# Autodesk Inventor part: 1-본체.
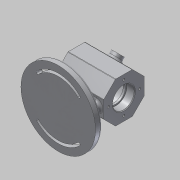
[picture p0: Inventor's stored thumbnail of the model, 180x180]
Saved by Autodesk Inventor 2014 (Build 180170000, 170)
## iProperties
Created: 2017-06
Part Number: 1-본체.
Material: Aluminum 6061
Document SubType Name: Modeling
Designer: Administrator
Density: 2.71 g/cm^3
Appearance: Aluminum - Flat
Mass: 562.518 g
Surface Area: 565.55 cm^2
Volume: 207.571 cm^3
Author: Administrator
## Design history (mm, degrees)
sketch "Sketch1"
  geometry: L1 (92, -12.426)-(74.426, -30); L2 (74.426, -30)-(49.574, -30); L3 (49.574, -30)-(32, -12.426); L4 (32, -12.426)-(32, 12.426); L5 (32, 12.426)-(49.574, 30); L6 (49.574, 30)-(74.426, 30); L7 (74.426, 30)-(92, 12.426); L8 (92, 12.426)-(92, -12.426); L9 (92, -12.426)-(62, 0); L10 (92, 12.426)-(62, 0); C1 r 30 at (62, 0); 1 further point
  constraints: 20 end point, 1 centre point, 1 coincident, 1 horizontal, 1 tangent, 17 other
  dimensions: "d2" = 60 diameter of C1; "d3" = 45 deg angle of L10 L9 (derived); "d4" = 62 distance of C1.centre point (0, 0); "d5" = 92 horizontal distance of point (0, 0) L1.start
extrude "Extrusion1" new body sketch "Sketch1" stored distance "d6" = 70; taper "d7" = 0 deg
sketch "Sketch2"
  geometry: C1 r 55 at (0, 0); 1 further point
  constraints: 1 centre point, 1 coincident
  dimensions: "d8" = 110 diameter of C1
extrude "Extrusion2" join sketch "Sketch2" distance "d9" = 10; taper "d10" = 0 deg
sketch "Sketch3"
  geometry: L1 (-35, 62)-(35, 62); L2 (-35, 62)-(-35, 78); L3 (-35, 78)-(-23, 78); L4 (-23, 78)-(-23, 76); L5 (-23, 76)-(-20, 76); L6 (-20, 76)-(-20, 87); L7 (-20, 87)-(20, 87); L8 (20, 87)-(20, 76); L9 (20, 76)-(23, 76); L10 (23, 76)-(23, 78); L11 (23, 78)-(35, 78); L12 (35, 78)-(35, 62); 1 further point
  constraints: 24 end point, 11 perpendicular, 1 horizontal
  dimensions: "d12" = 12 distance of L2.end L3.end; "d14" = 3 distance of L5.end L4.end; "d16" = 40 distance of L6.end L7.end; "d17" = 3 distance of L8.end L9.end; "d19" = 32 diameter of L2.end L1; "d21" = 28 diameter of L4.end L1; "d22" = 50 diameter of L6.end L1; "d23" = 32 diameter of L11.end L1; "d24" = 28 diameter of L9.end L1; "d25" = 12 distance between parallel lines of L12 L10; "d26" = 35 distance from line of point (0, 0) L12; "d27" = 78 distance from line of point (0, 0) L11
revolve "Revolution1" sketch "Sketch3" stored, may be unused: angle "d28" = 90 deg
sketch "Sketch4"
  geometry: 5 further points
sketch "Sketch5"
  geometry: 5 further points
hole "Hole1" sketch "Sketch4" diameter "d31" = 3.242; stored, may be unused: countersink angle "d35" = 90 deg, drill point angle "d37" = 118 deg; dims "d32" = 8, "d33" = 4, "d34" = 2, "d36" = 10
hole "Hole2" sketch "Sketch5" diameter "d38" = 3.242; stored, may be unused: countersink angle "d42" = 90 deg, drill point angle "d44" = 118 deg; dims "d39" = 8, "d40" = 4, "d41" = 2, "d43" = 10
workplane "Work Plane1"
sketch "Sketch6"
  geometry: C1 r 8 at (35, 12.426); 2 further points
  constraints: 1 centre point
  dimensions: "d47" = 16 diameter of C1; "d48" = 35 horizontal distance of C1.centre point (0, 24.853); "d49" = 43.84062 distance of point (35, -31.414) C1.centre
extrude "Extrusion3" join sketch "Sketch6" stored distance "d50" = 10; taper "d51" = 0 deg
sketch "Sketch7"
  geometry: C1 r 4 at (0, 0); C2 r 8 at (0, 0) reference; 1 further point
  constraints: 1 centre point, 1 concentric
  dimensions: "d52" = 8 diameter of C1
extrude "Extrusion4" cut sketch "Sketch7" distance "d53" = 20; taper "d54" = 0 deg
sketch "Sketch8"
  geometry: C1 r 55 at (0, 0) reference; A1 r 2 centre (-30.406, 30.406) between (-31.82, 31.82) and (-28.991, 28.991); A2 r 2 centre (30.406, 30.406) between (28.991, 28.991) and (31.82, 31.82); A3 r 45 centre (0, 0) between (31.82, 31.82) and (-31.82, 31.82); A4 r 41 centre (0, 0) between (28.991, 28.991) and (-28.991, 28.991)
  constraints: 8 point on circle, 4 centre point, 4 tangent, 1 coincident, 1 concentric
  dimensions: "d62" = 2 radius of A2; "d63" = 45 radius of A3; "d64" = 60.87693 distance of A2.end A1.end
extrude "Extrusion5" cut sketch "Sketch8" distance "d65" = 7; taper "d66" = 0 deg
sketch "Sketch9"
  geometry: C1 r 55 at (0, 0) reference; A1 r 5 centre (30.406, -30.406) between (33.941, -33.941) and (26.87, -26.87); A2 r 5 centre (-30.406, -30.406) between (-26.87, -26.87) and (-33.941, -33.941); A3 r 38 centre (0, 0) between (-26.87, -26.87) and (26.87, -26.87); A4 r 48 centre (0, 0) between (-33.941, -33.941) and (33.941, -33.941)
  constraints: 8 point on circle, 4 centre point, 3 tangent, 1 coincident, 1 concentric
  dimensions: "d72" = 10 diameter of A1; "d73" = 10 diameter of A2; "d74" = 48 radius of A4; "d78" = 61.22091 distance of A1.start A2.start
extrude "Extrusion6" cut sketch "Sketch9" distance "d76" = 3; taper "d77" = 0 deg
mirror "Mirror1"
sketch "Sketch10"
  geometry: L1 (-24, 5)-(24, 5); L2 (-24, -5)-(24, -5); A1 r 5 centre (-24, 0) between (-24, 5) and (-24, -5); A2 r 5 centre (24, 0) between (24, -5) and (24, 5); 1 further point
  constraints: 4 end point, 4 point on circle, 4 tangent, 2 centre point, 1 horizontal
  dimensions: "d81" = 10 diameter of A1; "d82" = 10 diameter of A2; "d83" = 48 distance of A2.centre A1.centre; "d84" = 28.94113 distance from line of point (33.941, 33.941) L1; "d85" = 38.94113 distance from line of point (33.941, 33.941) L2
extrude "Extrusion7" join sketch "Sketch10" stored distance "d86" = 3; taper "d87" = 0 deg
chamfer "Chamfer1" distance "d88" = 1; stored, may be unused: second distance "d89" = 2, angle "d90" = 45 deg
chamfer "Chamfer2" distance "d91" = 1; stored, may be unused: second distance "d92" = 2, angle "d93" = 45 deg
chamfer "Chamfer3" distance "d96" = 1; stored, may be unused: second distance "d97" = 2, angle "d98" = 45 deg
fillet "Fillet1" dims "d94" = 3, "d95" = 0.3, "d99" = 5, "d104" = 1
sketch "Sketch11"
  geometry: 3 further points
  constraints: 1 other
  dimensions: "d100" = 35 horizontal distance of point (35, 12.426) point (0, 42.426); "d101" = 30 vertical distance of point (35, 12.426) point (0, 42.426)
emboss "Emboss1" sketch "Sketch11" dims "d12" = 12, "d14" = 3, "d16" = 40, "d17" = 3, "d19" = 32, "d21" = 28, "d22" = 50, "d23" = 32, "d24" = 28, "d25" = 12, "d26" = 35, "d27" = 78, "d102" = 0.5, "d103" = 0
body "Solid1"
other parameters: "d45" = 7, "d59" = 86
